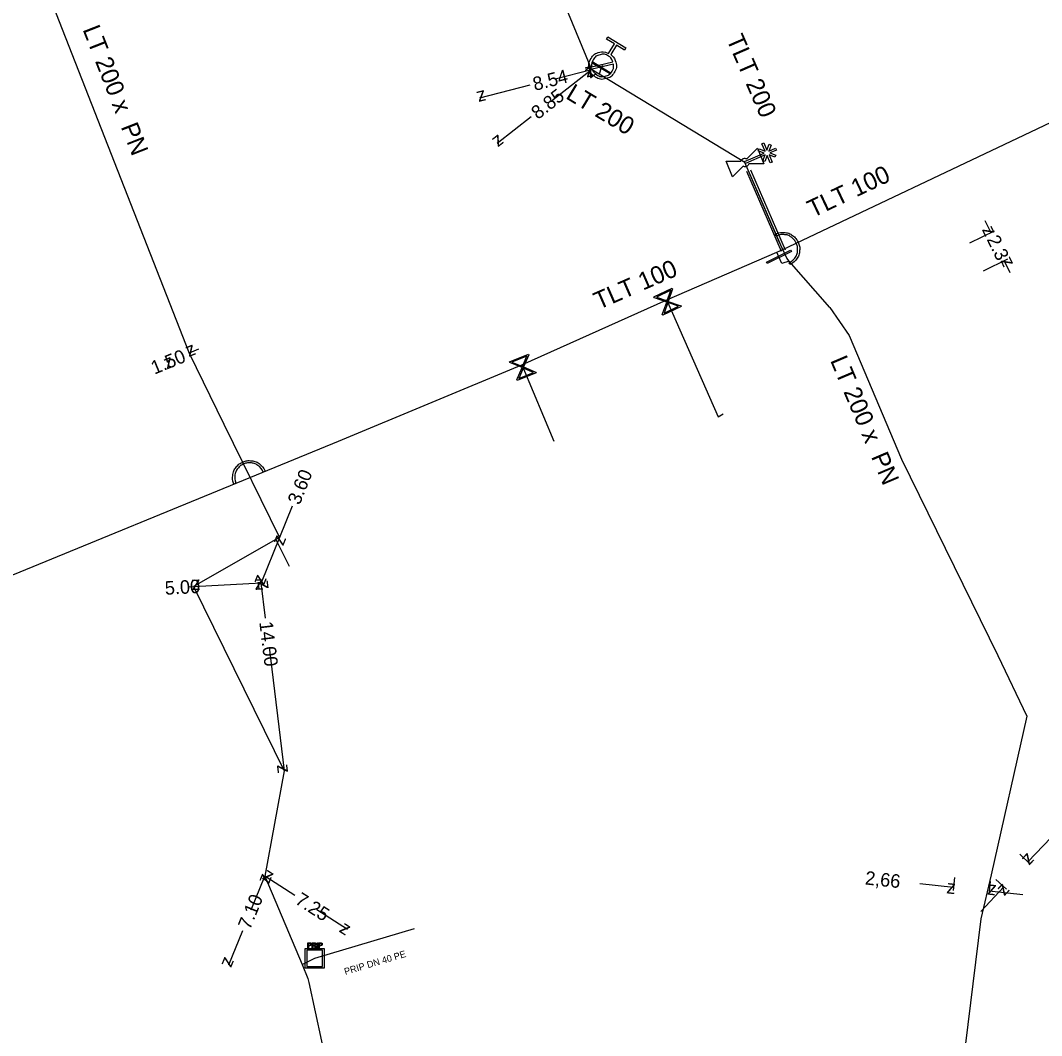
# Model space of a CAD drawing. Extents: x -643842 to -636370, y -1119190 to -1110210.
# Drawn here: x -641372.7 to -641297.3, y -1114116.3 to -1114041.3 of the extents above; entities that cross this region are included whole.
import ezdxf

# ---------------------------------------------------------------- set-up
doc = ezdxf.new("R2010")
doc.units = 0
for name, color, linetype in [('2', 7, 'Continuous'), ('22', 7, 'Continuous'), ('9', 7, 'Continuous'), ('Default', 7, 'Continuous'), ('Level 10', 7, 'Continuous'), ('Level 16', 7, 'Continuous'), ('Level 18', 7, 'Continuous'), ('Level 20', 7, 'Continuous'), ('Level 21', 7, 'Continuous'), ('Level 23', 7, 'Continuous'), ('Level 28', 7, 'Continuous'), ('Level 29', 7, 'Continuous'), ('Level 30', 7, 'Continuous'), ('Level 33', 7, 'Continuous')]:
    doc.layers.add(name, color=color, linetype=linetype)

msp = doc.modelspace()

# ---------------------------------------------------------------- linework, layer by layer
at = {"layer": '2'}
msp.add_lwpolyline([(-641317.448, -1114050.932), (-641316.953, -1114050.716), (-641316.891, -1114050.86), (-641317.381, -1114051.073), (-641316.944, -1114051.244), (-641317.002, -1114051.389), (-641317.436, -1114051.219), (-641317.206, -1114051.748), (-641317.349, -1114051.81), (-641317.583, -1114051.273), (-641317.755, -1114051.714), (-641317.9, -1114051.657), (-641317.731, -1114051.225), (-641319.183, -1114051.857), (-641319.245, -1114051.714), (-641317.789, -1114051.08), (-641318.229, -1114050.908), (-641318.171, -1114050.763), (-641317.729, -1114050.936), (-641317.963, -1114050.4), (-641317.819, -1114050.337), (-641317.59, -1114050.864), (-641317.42, -1114050.433), (-641317.275, -1114050.49), (-641317.448, -1114050.932)], dxfattribs=at)
at = {"layer": '9'}
for points in [[(-641316.885, -1114057.21), (-641316.951, -1114057.069)], [(-641315.889, -1114059.332), (-641315.956, -1114059.191)], [(-641354.66, -1114074.6), (-641354.804, -1114074.66)], [(-641356.828, -1114075.49), (-641356.973, -1114075.55)]]:
    msp.add_lwpolyline(points, dxfattribs=at)
at = {"layer": 'Default'}
for points in [[(-641329.133, -1114043.807), (-641328.842, -1114044.019), (-641328.757, -1114044.375), (-641328.661, -1114044.777), (-641328.878, -1114045.132), (-641329.093, -1114045.485), (-641329.495, -1114045.582), (-641329.898, -1114045.679), (-641330.253, -1114045.462), (-641330.605, -1114045.248), (-641330.703, -1114044.846), (-641330.801, -1114044.444), (-641330.585, -1114044.09), (-641330.368, -1114043.735), (-641329.967, -1114043.637), (-641329.611, -1114043.547), (-641329.29, -1114043.711)], [(-641328.965, -1114044.33), (-641329.058, -1114044.066), (-641329.308, -1114043.913), (-641329.596, -1114043.737), (-641329.923, -1114043.816), (-641330.249, -1114043.895), (-641330.425, -1114044.184), (-641330.577, -1114044.434), (-641330.538, -1114044.711)], [(-641330.495, -1114044.889), (-641330.401, -1114045.15), (-641330.154, -1114045.3), (-641329.867, -1114045.475), (-641329.54, -1114045.397), (-641329.213, -1114045.318), (-641329.037, -1114045.03), (-641328.887, -1114044.783), (-641328.922, -1114044.507)], [(-641319.512, -1114051.684), (-641319.496, -1114051.634), (-641319.462, -1114051.591), (-641319.41, -1114051.525), (-641319.334, -1114051.494), (-641319.259, -1114051.462), (-641319.172, -1114051.473), (-641319.12, -1114051.479), (-641319.073, -1114051.503)], [(-641318.917, -1114051.882), (-641318.934, -1114051.931), (-641318.967, -1114051.973), (-641319.021, -1114052.04), (-641319.097, -1114052.072), (-641319.172, -1114052.103), (-641319.256, -1114052.092), (-641319.31, -1114052.085), (-641319.357, -1114052.061)], [(-641316.951, -1114057.069), (-641316.655, -1114056.931), (-641316.312, -1114056.954), (-641315.969, -1114056.979), (-641315.696, -1114057.181), (-641315.424, -1114057.382), (-641315.289, -1114057.669), (-641315.156, -1114057.954), (-641315.174, -1114058.293), (-641315.193, -1114058.632), (-641315.393, -1114058.912), (-641315.594, -1114059.192), (-641315.889, -1114059.332)], [(-641315.956, -1114059.191), (-641315.697, -1114059.068), (-641315.522, -1114058.823), (-641315.347, -1114058.577), (-641315.33, -1114058.281), (-641315.314, -1114057.985), (-641315.431, -1114057.735), (-641315.548, -1114057.485), (-641315.787, -1114057.308), (-641316.026, -1114057.131), (-641316.325, -1114057.11), (-641316.625, -1114057.09), (-641316.885, -1114057.21)], [(-641356.973, -1114075.55), (-641357.096, -1114075.246), (-641357.056, -1114074.906), (-641357.014, -1114074.564), (-641356.799, -1114074.301), (-641356.584, -1114074.039), (-641356.292, -1114073.919), (-641356.001, -1114073.799), (-641355.663, -1114073.835), (-641355.325, -1114073.871), (-641355.055, -1114074.084), (-641354.785, -1114074.298), (-641354.66, -1114074.6)], [(-641354.804, -1114074.66), (-641354.914, -1114074.395), (-641355.151, -1114074.208), (-641355.387, -1114074.021), (-641355.682, -1114073.99), (-641355.977, -1114073.959), (-641356.233, -1114074.064), (-641356.488, -1114074.168), (-641356.677, -1114074.398), (-641356.865, -1114074.628), (-641356.901, -1114074.926), (-641356.936, -1114075.224), (-641356.828, -1114075.49)], [(-641351.38, -1114109.465), (-641351.344, -1114109.465), (-641351.325, -1114109.469), (-641351.299, -1114109.474), (-641351.281, -1114109.486), (-641351.262, -1114109.498), (-641351.252, -1114109.52), (-641351.242, -1114109.542), (-641351.242, -1114109.569), (-641351.242, -1114109.615), (-641351.27, -1114109.646), (-641351.299, -1114109.677), (-641351.375, -1114109.677)], [(-641351.375, -1114109.636), (-641351.328, -1114109.636), (-641351.309, -1114109.619), (-641351.291, -1114109.602), (-641351.291, -1114109.57), (-641351.291, -1114109.548), (-641351.302, -1114109.532), (-641351.313, -1114109.516), (-641351.331, -1114109.511), (-641351.343, -1114109.508), (-641351.376, -1114109.508)], [(-641350.985, -1114109.749), (-641351.006, -1114109.716), (-641351.02, -1114109.699), (-641351.033, -1114109.682), (-641351.044, -1114109.676), (-641351.055, -1114109.669), (-641351.066, -1114109.666), (-641351.073, -1114109.664), (-641351.092, -1114109.664)], [(-641351.045, -1114109.624), (-641351.012, -1114109.624), (-641350.994, -1114109.617), (-641350.976, -1114109.61), (-641350.966, -1114109.596), (-641350.957, -1114109.581), (-641350.957, -1114109.563), (-641350.957, -1114109.538), (-641350.976, -1114109.522), (-641350.994, -1114109.505), (-641351.034, -1114109.505)], [(-641351.035, -1114109.465), (-641350.988, -1114109.465), (-641350.963, -1114109.475), (-641350.938, -1114109.485), (-641350.923, -1114109.509), (-641350.908, -1114109.533), (-641350.908, -1114109.563), (-641350.908, -1114109.602), (-641350.933, -1114109.627), (-641350.957, -1114109.653), (-641351.009, -1114109.66), (-641350.99, -1114109.67), (-641350.98, -1114109.679), (-641350.96, -1114109.697), (-641350.941, -1114109.726)], [(-641350.578, -1114109.466), (-641350.542, -1114109.466), (-641350.523, -1114109.47), (-641350.497, -1114109.475), (-641350.479, -1114109.487), (-641350.46, -1114109.499), (-641350.45, -1114109.521), (-641350.44, -1114109.543), (-641350.44, -1114109.57), (-641350.44, -1114109.616), (-641350.468, -1114109.647), (-641350.497, -1114109.679), (-641350.573, -1114109.679)], [(-641350.573, -1114109.637), (-641350.526, -1114109.637), (-641350.507, -1114109.62), (-641350.489, -1114109.603), (-641350.489, -1114109.571), (-641350.489, -1114109.549), (-641350.5, -1114109.533), (-641350.511, -1114109.517), (-641350.529, -1114109.513), (-641350.541, -1114109.509), (-641350.574, -1114109.509)]]:
    msp.add_open_spline(points, degree=3, dxfattribs=at)
at = {"layer": 'Level 10'}
for points in [[(-641333.5, -1114047.213), (-641330.559, -1114044.904)], [(-641333.241, -1114045.59), (-641330.559, -1114044.904)], [(-641335.106, -1114046.066), (-641338.832, -1114047.019)], [(-641335.014, -1114048.402), (-641337.52, -1114050.37)], [(-641301.491, -1114056.065), (-641301.055, -1114056.965)], [(-641302.59, -1114057.709), (-641300.785, -1114056.834)], [(-641301.586, -1114059.778), (-641299.782, -1114058.903)], [(-641299.615, -1114059.934), (-641300.052, -1114059.034)], [(-641359.578, -1114065.585), (-641360.272, -1114065.87)], [(-641352.673, -1114077.191), (-641353.608, -1114079.513)], [(-641353.608, -1114079.513), (-641354.953, -1114082.853)], [(-641360.314, -1114083.145), (-641359.945, -1114083.125)], [(-641359.945, -1114083.125), (-641354.953, -1114082.853)], [(-641354.633, -1114085.456), (-641354.953, -1114082.853)], [(-641354.367, -1114087.617), (-641353.245, -1114096.748)], [(-641296.602, -1114101.672), (-641298.322, -1114103.486)], [(-641298.916, -1114102.922), (-641298.141, -1114103.658)], [(-641355.7, -1114107.031), (-641354.676, -1114104.544)], [(-641352.464, -1114105.961), (-641354.676, -1114104.544)], [(-641306.292, -1114105.086), (-641303.807, -1114105.357)], [(-641303.728, -1114104.638), (-641303.834, -1114105.605)], [(-641301.088, -1114104.925), (-641301.193, -1114105.893)], [(-641300.671, -1114104.772), (-641299.896, -1114105.508)], [(-641301.797, -1114107.15), (-641300.077, -1114105.336)], [(-641298.681, -1114105.915), (-641301.166, -1114105.644)], [(-641350.843, -1114107), (-641348.571, -1114108.455)], [(-641356.342, -1114108.589), (-641357.38, -1114111.11)]]:
    msp.add_lwpolyline(points, dxfattribs=at)
at = {"layer": 'Level 16'}
for points in [[(-641330.445, -1114044.35), (-641329.164, -1114045.131), (-641329.213, -1114045.211), (-641330.494, -1114044.43), (-641330.445, -1114044.35)], [(-641315.785, -1114058.362), (-641317.578, -1114059.248), (-641317.633, -1114059.136), (-641315.84, -1114058.25), (-641315.785, -1114058.362)], [(-641323.936, -1114062.422), (-641325.29, -1114063.069), (-641325.318, -1114063.01), (-641325.271, -1114062.89), (-641324.993, -1114062.097), (-641325.908, -1114061.775), (-641325.937, -1114061.716), (-641324.584, -1114061.069), (-641324.555, -1114061.128), (-641324.88, -1114062.044), (-641324.088, -1114062.322), (-641323.965, -1114062.362), (-641323.936, -1114062.422)], [(-641325.759, -1114061.735), (-641324.963, -1114062.014), (-641324.685, -1114061.221), (-641325.759, -1114061.735)], [(-641324.119, -1114062.405), (-641324.91, -1114062.127), (-641325.187, -1114062.916), (-641324.119, -1114062.405)], [(-641334.648, -1114067.33), (-641336.038, -1114067.894), (-641336.063, -1114067.833), (-641336.009, -1114067.716), (-641335.683, -1114066.942), (-641336.577, -1114066.565), (-641336.602, -1114066.504), (-641335.212, -1114065.94), (-641335.187, -1114066.001), (-641335.568, -1114066.896), (-641334.794, -1114067.222), (-641334.673, -1114067.269), (-641334.648, -1114067.33)], [(-641336.426, -1114066.534), (-641335.649, -1114066.861), (-641335.322, -1114066.086), (-641336.426, -1114066.534)], [(-641334.829, -1114067.303), (-641335.602, -1114066.977), (-641335.927, -1114067.748), (-641334.829, -1114067.303)]]:
    msp.add_lwpolyline(points, dxfattribs=at)
at = {"layer": 'Level 18'}
for points in [[(-641351.514, -1114109.824), (-641351.514, -1114109.465), (-641351.38, -1114109.465)], [(-641351.375, -1114109.677), (-641351.468, -1114109.677), (-641351.468, -1114109.824), (-641351.514, -1114109.824)], [(-641351.376, -1114109.508), (-641351.468, -1114109.508), (-641351.468, -1114109.636)], [(-641351.468, -1114109.636), (-641351.375, -1114109.636)], [(-641351.194, -1114109.824), (-641351.194, -1114109.465), (-641351.035, -1114109.465)], [(-641351.092, -1114109.664), (-641351.146, -1114109.664), (-641351.146, -1114109.824), (-641351.194, -1114109.824)], [(-641351.034, -1114109.505), (-641351.146, -1114109.505), (-641351.146, -1114109.624)], [(-641351.146, -1114109.624), (-641351.045, -1114109.624)], [(-641350.83, -1114109.825), (-641350.83, -1114109.466), (-641350.784, -1114109.466), (-641350.784, -1114109.825), (-641350.83, -1114109.825)], [(-641350.712, -1114109.825), (-641350.712, -1114109.466), (-641350.578, -1114109.466)], [(-641350.573, -1114109.679), (-641350.666, -1114109.679), (-641350.666, -1114109.825), (-641350.712, -1114109.825)], [(-641350.574, -1114109.509), (-641350.666, -1114109.509), (-641350.666, -1114109.637)], [(-641350.666, -1114109.637), (-641350.573, -1114109.637)], [(-641350.293, -1114109.887), (-641350.293, -1114111.339), (-641351.707, -1114111.339), (-641351.707, -1114109.887), (-641350.293, -1114109.887)], [(-641351.586, -1114110.011), (-641351.586, -1114111.215), (-641350.414, -1114111.215), (-641350.414, -1114110.011), (-641351.586, -1114110.011)], [(-641350.941, -1114109.726), (-641350.879, -1114109.824), (-641350.939, -1114109.824), (-641350.985, -1114109.749)]]:
    msp.add_lwpolyline(points, dxfattribs=at)
at = {"layer": 'Level 21'}
for points in [[(-641353.554, -1113988.95), (-641352.589, -1113991.545), (-641339.375, -1114023.452), (-641332.389, -1114040.452), (-641330.559, -1114044.904)], [(-641385.39, -1114001.782), (-641385.2, -1114002.279), (-641376.644, -1114024.107), (-641360.272, -1114065.87), (-641357.709, -1114071.118)], [(-641319.215, -1114051.783), (-641329.984, -1114045.253), (-641330.559, -1114044.904)], [(-641316.42, -1114058.2), (-641297.62, -1114049.28), (-641289.94, -1114045.63)], [(-641316.42, -1114058.2), (-641316.732, -1114057.528), (-641319.215, -1114051.783)], [(-641457.529, -1114115.488), (-641431.79, -1114105.42), (-641400.41, -1114092.71), (-641379.39, -1114084.75), (-641349.25, -1114072.38), (-641335.69, -1114066.74), (-641324.98, -1114061.93), (-641316.862, -1114058.399), (-641316.42, -1114058.2)], [(-641315.958, -1114059.071), (-641316.483, -1114059.258), (-641316.709, -1114058.749), (-641316.862, -1114058.399)], [(-641312.941, -1114062.501), (-641315.958, -1114059.071), (-641316.127, -1114058.851), (-641316.42, -1114058.2)], [(-641312.941, -1114062.501), (-641311.519, -1114064.575), (-641307.641, -1114073.709), (-641300.532, -1114088.229), (-641298.4, -1114092.703), (-641301.034, -1114104.428), (-641301.795, -1114107.688)], [(-641357.709, -1114071.118), (-641353.608, -1114079.513)], [(-641353.608, -1114079.513), (-641353.861, -1114079.657), (-641359.945, -1114083.125), (-641353.245, -1114096.748), (-641354.676, -1114104.544), (-641351.927, -1114111.077), (-641351.5, -1114112.09)], [(-641301.795, -1114107.688), (-641304.49, -1114129.72), (-641306.09, -1114146.01), (-641311.536, -1114174.051), (-641316.186, -1114189.268), (-641317.653, -1114199.52), (-641320.41, -1114215.01), (-641323.71, -1114228.17), (-641325.05, -1114233.24), (-641327.731, -1114241.931), (-641332.01, -1114258.52), (-641339.17, -1114286.33), (-641344.7, -1114307.58), (-641348.34, -1114321.37)], [(-641351.5, -1114112.09), (-641351.435, -1114112.391), (-641348.15, -1114127.57), (-641343.87, -1114139.91), (-641340.12, -1114154.08), (-641332.824, -1114169.762), (-641327.42, -1114181.96), (-641320.272, -1114199.061), (-641319.482, -1114201.216), (-641317.05, -1114206.76), (-641310.972, -1114243.12), (-641315.207, -1114249.378), (-641327.161, -1114279.989), (-641333.31, -1114292.811), (-641338.439, -1114303.506), (-641345.87, -1114322.41)]]:
    msp.add_lwpolyline(points, dxfattribs=at)
at = {"layer": 'Level 23'}
for points in [[(-641329.73, -1114044.61), (-641329.83, -1114044.78), (-641329.984, -1114045.253)], [(-641324.98, -1114061.93), (-641324.937, -1114062.069), (-641321.183, -1114070.576), (-641320.822, -1114070.37)], [(-641335.69, -1114066.74), (-641335.626, -1114066.918), (-641333.342, -1114072.369)], [(-641353.861, -1114079.657), (-641352.877, -1114081.632)], [(-641351.927, -1114111.077), (-641351, -1114110.61), (-641343.638, -1114108.413)]]:
    msp.add_lwpolyline(points, dxfattribs=at)
at = {"layer": 'Level 28'}
for points in [[(-641319.073, -1114051.503), (-641318.297, -1114050.729)], [(-641318.297, -1114050.729), (-641317.822, -1114051.885), (-641318.917, -1114051.882)], [(-641319.357, -1114052.061), (-641320.134, -1114052.836), (-641320.609, -1114051.68), (-641319.512, -1114051.684)]]:
    msp.add_lwpolyline(points, dxfattribs=at)
at = {"layer": 'Level 29'}
for points in [[(-641318.811, -1114052.331), (-641316.245, -1114058.228)], [(-641316.52, -1114058.348), (-641319.086, -1114052.451)]]:
    msp.add_lwpolyline(points, dxfattribs=at)
at = {"layer": 'Level 30'}
msp.add_lwpolyline([(-641316.382, -1114058.288), (-641318.948, -1114052.391)], dxfattribs=at)
at = {"layer": 'Level 33'}
for points in [[(-641329.29, -1114043.711), (-641328.863, -1114043.011), (-641329.452, -1114042.652), (-641329.356, -1114042.495), (-641328.022, -1114043.309), (-641328.118, -1114043.465), (-641328.706, -1114043.106), (-641329.133, -1114043.807)], [(-641330.538, -1114044.711), (-641328.965, -1114044.33)], [(-641328.922, -1114044.507), (-641330.495, -1114044.889)]]:
    msp.add_lwpolyline(points, dxfattribs=at)

# ---------------------------------------------------------------- texts
at = {"layer": '22'}
msp.add_text('PRIP DN 40 PE', height=0.5, rotation=16.61641, dxfattribs=at).set_placement((-641348.736, -1114111.845))
at = {"layer": 'Level 10'}
for s, rotation, p in [('z', 38.14014, (-641330.643, -1114045.606)), ('z', 14.34056, (-641330.92, -1114045.512)), ('8.54', 14.34056, (-641334.74, -1114046.489)), ('8.85', 38.14014, (-641334.509, -1114048.641)), ('z', 194.34054, (-641338.471, -1114046.411)), ('z', 218.14012, (-641337.436, -1114049.668)), ('z', 295.87353, (-641301.723, -1114056.733)), ('2.3', 295.87357, (-641301.374, -1114057.453)), ('z', 115.87355, (-641299.383, -1114059.266)), ('1.50', 22.32616, (-641362.844, -1114067.467)), ('z', 202.32614, (-641359.999, -1114065.218)), ('z', 22.32616, (-641361.933, -1114067.092)), ('3.60', 68.06561, (-641352.116, -1114077.146)), ('z', 68.06561, (-641353.331, -1114080.164)), ('z', 248.06565, (-641355.23, -1114082.202)), ('5.00', 3.11878, (-641362.046, -1114083.74)), ('z', 183.11882, (-641359.473, -1114082.599)), ('z', 3.11878, (-641355.425, -1114083.379)), ('z', 97.00777, (-641354.396, -1114083.288)), ('14.00', 277.00773, (-641355.099, -1114085.766)), ('z', 277.00775, (-641353.802, -1114096.313)), ('z', 226.51596, (-641298.341, -1114102.779)), ('z', 67.61721, (-641354.404, -1114105.197)), ('z', 147.35546, (-641353.985, -1114104.393)), ('2,66', 353.78991, (-641310.375, -1114105.145)), ('z', 353.78991, (-641304.358, -1114105.8)), ('z', 173.78991, (-641300.615, -1114105.201)), ('z', 46.51596, (-641300.058, -1114106.043)), ('7.10', 67.61721, (-641355.784, -1114108.549)), ('7.25', 327.35548, (-641352.523, -1114106.517)), ('z', 327.35544, (-641349.262, -1114108.606)), ('z', 247.61725, (-641357.652, -1114110.457))]:
    msp.add_text(s, height=1, rotation=rotation, dxfattribs=at).set_placement(p)
at = {"layer": 'Level 20'}
for s, rotation, p in [('LT 200 x  PN ', 291.40169, (-641368.163, -1114041.938)), ('TLT 200', 293.53608, (-641320.607, -1114042.653)), ('LT 200', 328.76737, (-641332.527, -1114047.003)), ('TLT 100', 25.38283, (-641314.213, -1114055.885)), ('TLT 100', 23.54507, (-641330.023, -1114062.683)), ('LT 200 x  PN ', 293.00454, (-641312.936, -1114066.405))]:
    msp.add_text(s, height=1.3, rotation=rotation, dxfattribs=at).set_placement(p)

doc.saveas('drawing.dxf')
